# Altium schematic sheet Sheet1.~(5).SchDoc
size A4; SheetNumber: 1; SheetTotal: 1
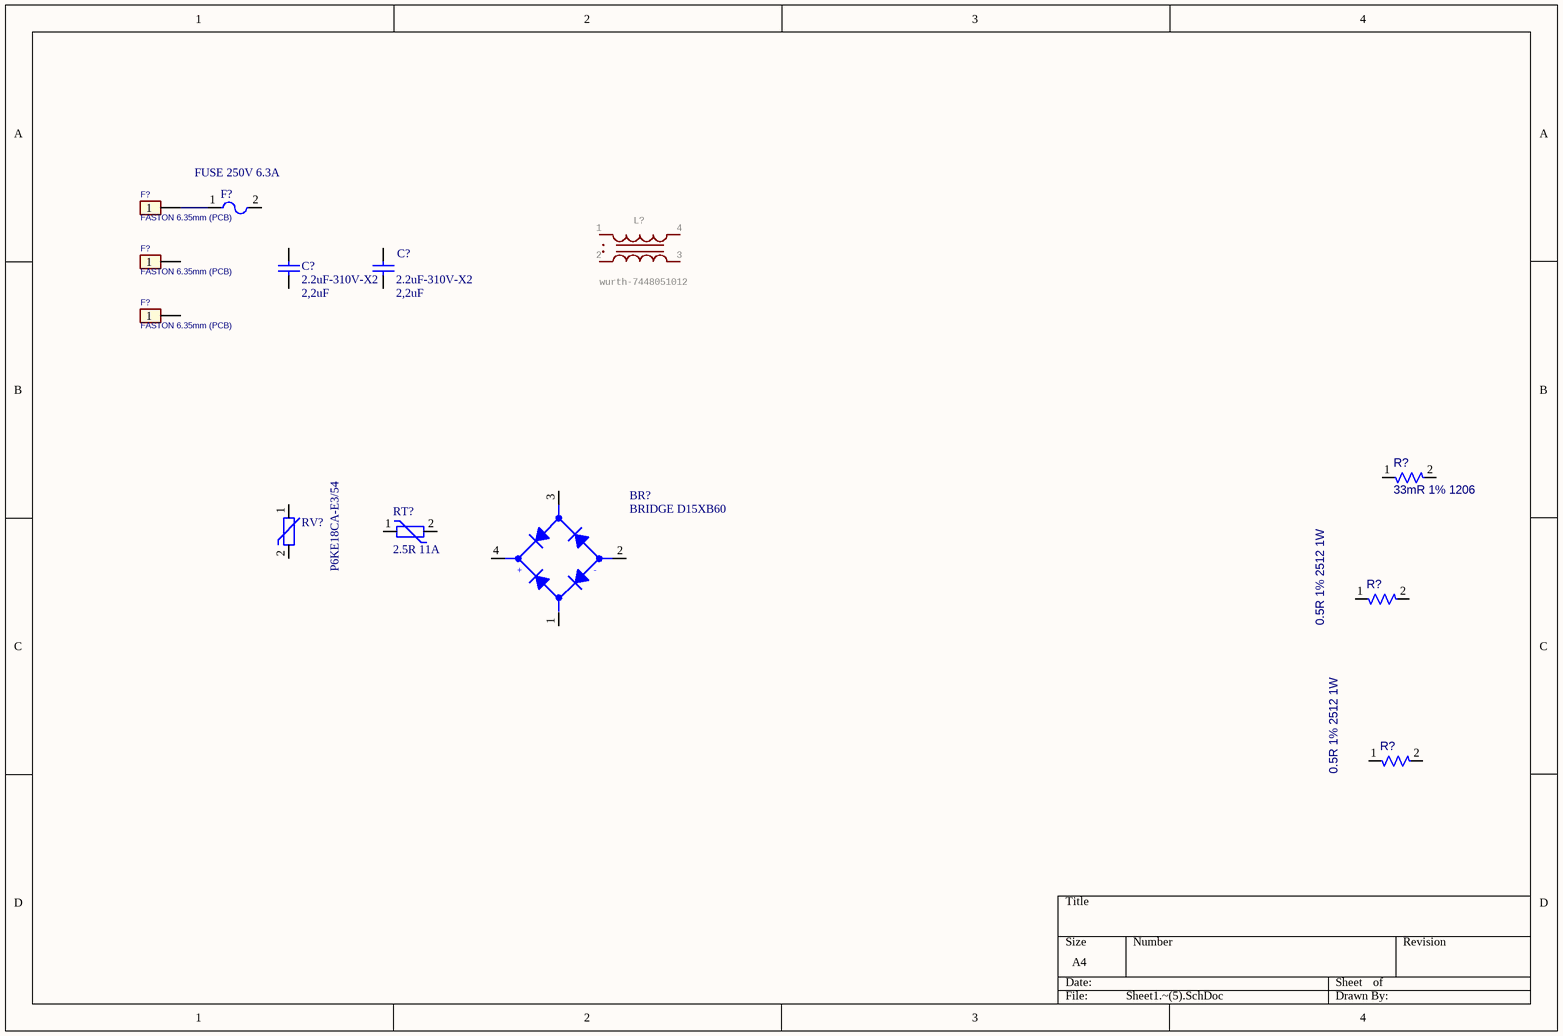
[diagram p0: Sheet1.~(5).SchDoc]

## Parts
(Parts that share a designator on the sheet are numbered #1, #2 ... from top to bottom, then left to right.)
BR?  BRIDGE D15XB60
C?#1  2.2uF-310V-X2  value 2,2uF
C?#2  2.2uF-310V-X2  value 2,2uF
F?#1  FASTON 6.35mm (PCB)  [FASTON_M_PCB_6.35x0.81]
F?#2  FUSE 250V 6.3A  [BEL_FUSE_0697A6300-01]
F?#3  FASTON 6.35mm (PCB)  [FASTON_M_PCB_6.35x0.81]
F?#4  FASTON 6.35mm (PCB)  [FASTON_M_PCB_6.35x0.81]
L?  wurth-7448051012  [WE-CMBNC_XL_7448051012]
R?#1  33mR 1% 1206  [1206_UP_RES]
R?#2  0.5R 1% 2512 1W  [2512_up]
R?#3  0.5R 1% 2512 1W  [2512_up]
RT?  2.5R 11A
RV?  P6KE18CA-E3/54  [DO15]

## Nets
NetF?#1_1: F?#1.1 F?#2.1

Not connected (* = marked no-connect by the designer): BR? 1(AC1) 2(-DC) 3(AC2) 4(+DC); C?#1 1 2; C?#2 1 2; F?#2 2; F?#3 1; F?#4 1; L? 1 2 3 4; R?#1 1 2; R?#2 1 2; R?#3 1 2; RT? 1 2; RV? 1 2

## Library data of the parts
BR? = BRIDGE_D15XB60_15A_600V: BRIDGE D15XB60 15A 600V; Costo: 0; Aggiornato: NO
C?#1 C?#2 = Cap: 2.2uF-310V-X2  VISHAY F339M/52231MIM2T0
F?#1 F?#3 F?#4 = FASTON_M_PCB_6.35mm: FASTON M PCB 6.35mm; Hpcode: FASTMASCSTAMP; Costo: 0,01; Aggiornato: s; ContoLavoro: 0
F?#2 = FUSE_250V_6.3A_T_BEL_FUSE_0697A6300-01: FUSE 250Vac 6.3A Time Delay BEL FUSE 0697A6300-01; Costo: 0,26; Aggiornato: S; ContoLavoro: 0
L? = WE-CMBNC_XL_7448051012: GateName_1: G$1; IR: 10A; RDC: 15mOhm; VR: 250  V (AC); VT: 1500  V (AC)
R?#1 = R_0.33_1%_1206: 33mR 1% 1206 SMD RESISTOR; Value: 0.033; Costo: 0,17; Aggiornato: s; ContoLavoro: 0
R?#2 R?#3 = R_0.5R_1%_2512: 0.5R 1% 2512 1W SMD RESISTOR; Costo: 0,40; Value: 0.5; Aggiornato: s; ContoLavoro: 0
RT? = RT_2.5R_10A: NTC 2.5R 11A  TDK B57364S0259M0 21x7; Costo: 0; Aggiornato: NO
RV? = VARISTOR: VARISTORE VISHAY P6KE18CA-E3/54 ALT:RS 699-7972; Costo: 0,155; Aggiornato: NO; ContoLavoro: 0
